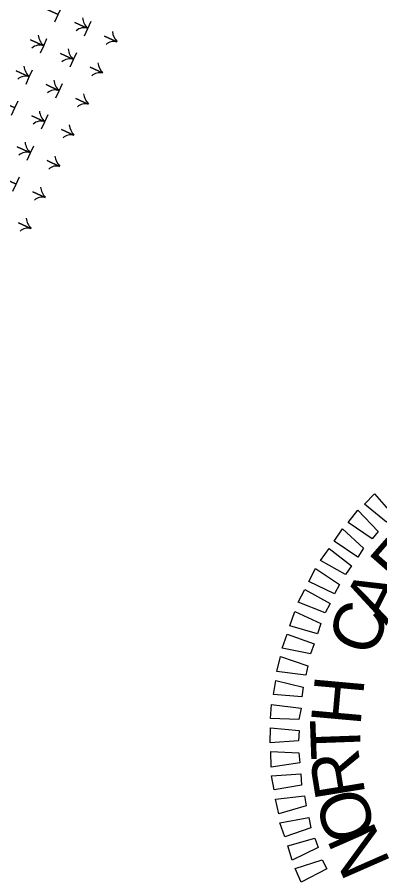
# Model space of a CAD drawing. Extents: x 2532037 to 2533565, y 713396 to 716867.
# Drawn here: x 2532994.2 to 2533092.7, y 715281.6 to 715515.5 of the extents above; entities that cross this region are included whole.
import ezdxf

# ---------------------------------------------------------------- set-up
doc = ezdxf.new("R2010")
doc.units = 0
doc.layers.add('Scratch_Level_1', color=7, linetype='Continuous')
doc.layers.add('Sheet Professional Seal CELL', color=7, linetype='Continuous')

msp = doc.modelspace()

# ---------------------------------------------------------------- linework, layer by layer
at = {"layer": 'Scratch_Level_1'}
for points in [[(2533004.34, 715514.2), (2533005.25, 715516.15), (2533001.66, 715517.81), (2533005.25, 715516.15), (2533006.15, 715518.11)], [(2533012.47, 715510.45), (2533013.37, 715512.41), (2533009.79, 715514.06), (2533013.37, 715512.41), (2533014.27, 715514.36)], [(2533000.45, 715505.76), (2533001.35, 715507.71), (2532997.77, 715509.36), (2533001.35, 715507.71), (2533002.25, 715509.66)], [(2533021.23, 715508.78), (2533017.91, 715510.31), (2533021.23, 715508.78)], [(2533008.57, 715502.01), (2533009.47, 715503.96), (2533005.89, 715505.61), (2533009.47, 715503.96), (2533010.37, 715505.91)], [(2532996.55, 715497.31), (2532997.45, 715499.27), (2532993.87, 715500.92), (2532997.45, 715499.27), (2532998.35, 715501.22)], [(2533017.34, 715500.33), (2533014.01, 715501.87), (2533017.34, 715500.33)], [(2533004.67, 715493.56), (2533005.57, 715495.52), (2533001.99, 715497.17), (2533005.57, 715495.52), (2533006.47, 715497.47)], [(2532992.65, 715488.87), (2532993.55, 715490.82), (2532989.97, 715492.48), (2532993.55, 715490.82), (2532994.45, 715492.77)], [(2533013.45, 715491.88), (2533010.11, 715493.42), (2533013.45, 715491.88)], [(2533000.77, 715485.12), (2533001.67, 715487.07), (2532998.09, 715488.73), (2533001.67, 715487.07), (2533002.57, 715489.02)], [(2533009.56, 715483.43), (2533006.21, 715484.98), (2533009.56, 715483.43)], [(2532996.87, 715476.68), (2532997.77, 715478.63), (2532994.19, 715480.28), (2532997.77, 715478.63), (2532998.68, 715480.58)], [(2533005.67, 715474.98), (2533002.31, 715476.53), (2533005.67, 715474.98)], [(2532992.97, 715468.23), (2532993.88, 715470.18), (2532990.29, 715471.84), (2532993.88, 715470.18), (2532994.78, 715472.14)], [(2533001.79, 715466.53), (2532998.41, 715468.09), (2533001.79, 715466.53)], [(2532997.9, 715458.08), (2532994.52, 715459.64), (2532997.9, 715458.08)]]:
    msp.add_lwpolyline(points, dxfattribs=at)
for centre, radius, start, end in [((2533016.65, 715515.91), 4.81, 187.3464, 226.8412), ((2533004.63, 715511.22), 4.81, 187.3464, 226.8412), ((2533012.28, 715509.53), 3.07, 69.3593, 132.7539), ((2533024.78, 715512.16), 4.81, 187.3464, 223.2016), ((2533020.41, 715505.78), 3.07, 74.7344, 132.7539), ((2533000.26, 715504.83), 3.07, 69.3593, 132.7539), ((2533012.76, 715507.47), 4.81, 187.3464, 226.8412), ((2533008.39, 715501.08), 3.07, 69.3593, 132.7539), ((2533000.74, 715502.77), 4.81, 187.3464, 226.8412), ((2533020.88, 715503.72), 4.81, 187.3464, 223.3419), ((2532996.37, 715496.39), 3.07, 69.3593, 132.7539), ((2533016.51, 715497.33), 3.07, 74.5283, 132.7539), ((2533008.86, 715499.02), 4.81, 187.3464, 226.8412), ((2533004.49, 715492.64), 3.07, 69.3593, 132.7539), ((2533016.98, 715495.27), 4.81, 187.3464, 223.4822), ((2533012.61, 715488.89), 3.07, 74.3222, 132.7539), ((2533004.96, 715490.58), 4.81, 187.3464, 226.8412), ((2533000.59, 715484.19), 3.07, 69.3593, 132.7539), ((2533013.08, 715486.83), 4.81, 187.3464, 223.6223), ((2533008.71, 715480.45), 3.07, 74.1163, 132.7539), ((2533001.06, 715482.13), 4.81, 187.3464, 226.8412), ((2532996.69, 715475.75), 3.07, 69.3593, 132.7539), ((2533009.18, 715478.38), 4.81, 187.3464, 223.7622), ((2533004.81, 715472), 3.07, 73.9105, 132.7539), ((2533005.28, 715469.94), 4.81, 187.3464, 223.9021), ((2533000.91, 715463.56), 3.07, 73.7048, 132.7539), ((2533001.39, 715461.5), 4.81, 187.3464, 224.0418), ((2532997.01, 715455.11), 3.07, 73.4993, 132.7539)]:
    msp.add_arc(centre, radius, start, end, dxfattribs=at)
at = {"layer": 'Sheet Professional Seal CELL'}
for points in [[(2533094.47, 715378.4), (2533088.55, 715383.26), (2533091.25, 715386.09), (2533096.32, 715380.31)], [(2533090.56, 715373.89), (2533084.06, 715378.36), (2533086.69, 715381.62), (2533092.2, 715375.9)], [(2533086.71, 715368.95), (2533080.26, 715373.26), (2533082.53, 715376.57), (2533088.29, 715371.39)], [(2533083.34, 715364.18), (2533076.53, 715368.01), (2533078.9, 715371.26), (2533085.03, 715366.57)], [(2533080.41, 715358.94), (2533073.39, 715362.33), (2533075.22, 715365.84), (2533081.77, 715361.48)], [(2533077.8, 715353.8), (2533070.52, 715356.65), (2533072.35, 715360.16), (2533079.16, 715356.34)], [(2533075.74, 715348.14), (2533068.24, 715350.28), (2533069.59, 715354.17), (2533076.66, 715350.89)], [(2533073.88, 715342.64), (2533066.13, 715344.24), (2533067.53, 715347.97), (2533074.81, 715345.39)], [(2533072.57, 715336.87), (2533064.66, 715337.89), (2533065.68, 715341.93), (2533073.12, 715339.4)], [(2533071.47, 715331.01), (2533063.78, 715331.65), (2533064.43, 715335.47), (2533071.81, 715333.64)], [(2533070.64, 715324.88), (2533063.02, 715325.09), (2533063.29, 715328.96), (2533071.3, 715327.89)], [(2533070.62, 715319.03), (2533062.9, 715318.49), (2533063, 715322.57), (2533070.79, 715321.87)], [(2533070.97, 715313.13), (2533063.2, 715311.95), (2533063.09, 715316.13), (2533070.66, 715315.81)], [(2533071.38, 715307.07), (2533063.94, 715305.73), (2533063.24, 715309.53), (2533071.23, 715310.07)], [(2533072.64, 715301.4), (2533065.21, 715299.25), (2533064.35, 715303.27), (2533072.22, 715304.13)], [(2533073.9, 715295.46), (2533066.85, 715293), (2533065.51, 715296.84), (2533073.38, 715298.24)], [(2533075.96, 715290.07), (2533068.87, 715286.69), (2533067.69, 715290.59), (2533075.07, 715292.63)], [(2533078.25, 715284.3), (2533071.32, 715280.72), (2533069.66, 715284.45), (2533077.03, 715286.75)]]:
    msp.add_lwpolyline(points, close=True, dxfattribs=at)

# ---------------------------------------------------------------- texts
for s, rotation, p in [('R', 48.8649, (2533099.3, 715359.15)), ('A', 63.2641, (2533094.49, 715350.28)), ('C', 70.4636, (2533091.02, 715341.43)), ('H', 84.8632, (2533087.42, 715322.91)), ('T', 92.0635, (2533087.59, 715314.17)), ('R', 99.2643, (2533088.8, 715304.52)), ('O', 106.4655, (2533091.91, 715293.83)), ('N', 113.6673, (2533095.78, 715285.84))]:
    msp.add_text(s, height=13.53, rotation=rotation, dxfattribs=at).set_placement(p)

doc.saveas('drawing.dxf')
